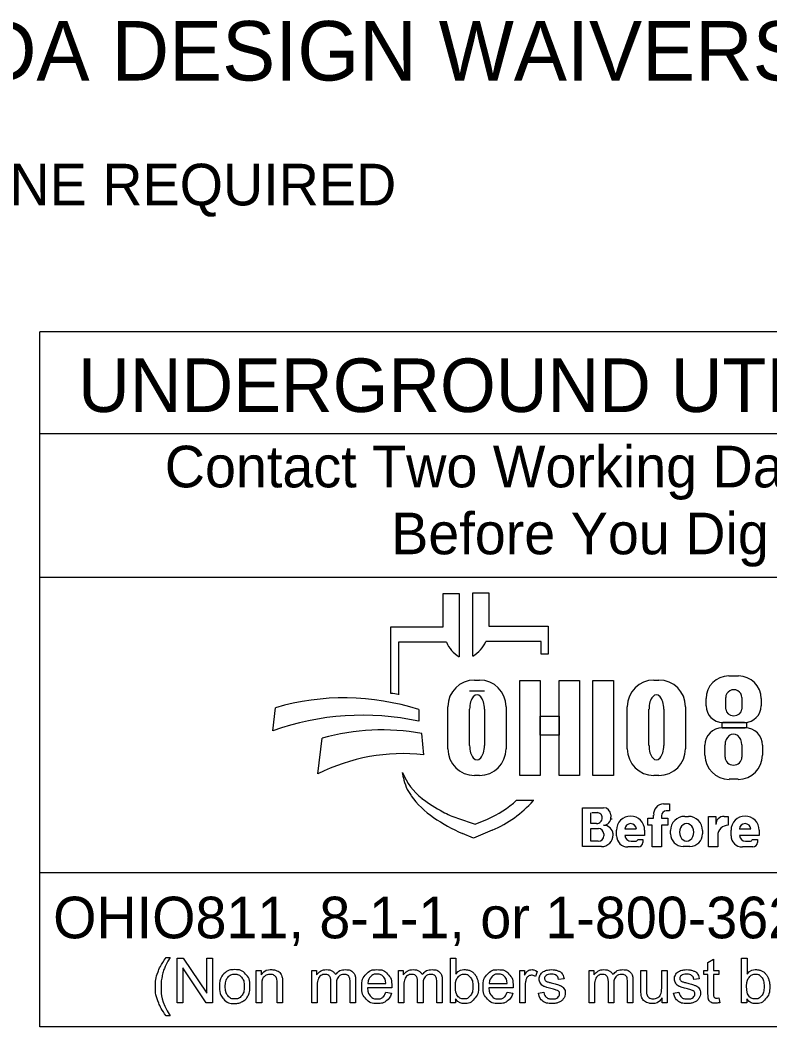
# Model space of a CAD drawing. Extents: x 6.3 to 40.3, y 9 to 31.
# Drawn here: x 8.656 to 11.176, y 11.189 to 14.574 of the extents above; entities that cross this region are included whole.
import ezdxf

# ---------------------------------------------------------------- set-up
doc = ezdxf.new("R2010")
doc.units = 0
doc.layers.add('SH_Data', color=7, linetype='Continuous')
doc.layers.add('SH_Text', color=7, linetype='Continuous')

msp = doc.modelspace()

# ---------------------------------------------------------------- linework, layer by layer
at = {"layer": 'SH_Data'}
for p, q in [((8.7221, 11.1885), (8.7221, 13.526)), ((12.9721, 13.526), (8.7221, 13.526)), ((8.7221, 13.1844), (12.9721, 13.1844)), ((8.7221, 12.7011), (12.9721, 12.7011)), ((12.9721, 11.7064), (8.7221, 11.7064)), ((12.9721, 11.1885), (8.7221, 11.1885))]:
    msp.add_line(p, q, dxfattribs=at)
at = {"layer": 'SH_Text'}
for p, q in [((10.0781, 12.534), (10.0781, 12.6455)), ((10.0781, 12.6455), (10.1318, 12.6455)), ((10.1318, 12.6455), (10.1318, 12.4334)), ((10.1775, 12.4358), (10.1775, 12.6478)), ((10.1775, 12.6478), (10.2311, 12.6478)), ((10.2311, 12.6478), (10.2311, 12.5364)), ((9.9022, 12.3101), (9.9022, 12.534)), ((9.9022, 12.534), (10.0781, 12.534)), ((10.2311, 12.5364), (10.4303, 12.5364)), ((10.4303, 12.5364), (10.4303, 12.4425)), ((9.9274, 12.4826), (9.9274, 12.3057)), ((10.0886, 12.4826), (9.9274, 12.4826)), ((10.4071, 12.4849), (10.2207, 12.4849)), ((10.4071, 12.4425), (10.4071, 12.4849)), ((10.4303, 12.4425), (10.4071, 12.4425)), ((11.0377, 12.3688), (11.0704, 12.3688)), ((10.1831, 12.3548), (10.1997, 12.3548)), ((10.7862, 12.3548), (10.8027, 12.3548)), ((10.2164, 12.3178), (10.1666, 12.3178)), ((10.9614, 12.2682), (10.9614, 12.2925)), ((11.0276, 12.2568), (11.0276, 12.2961)), ((11.0817, 12.2961), (11.0817, 12.2568)), ((11.1468, 12.2925), (11.1468, 12.2682)), ((9.5048, 12.1838), (9.5142, 12.262)), ((10.0937, 12.1234), (10.0937, 12.2654)), ((10.1666, 12.1348), (10.1666, 12.2571)), ((10.2164, 12.2571), (10.2164, 12.1348)), ((10.2891, 12.2654), (10.2891, 12.1234)), ((10.6967, 12.1234), (10.6967, 12.2654)), ((10.7696, 12.1348), (10.7696, 12.2571)), ((10.8194, 12.2571), (10.8194, 12.1348)), ((10.8922, 12.2654), (10.8922, 12.1234)), ((9.9955, 12.2555), (9.9955, 12.2166)), ((11.0156, 12.1939), (11.0929, 12.1939)), ((11.0908, 12.2122), (11.0174, 12.2122)), ((9.6566, 12.0393), (9.6713, 12.1594)), ((10.0054, 12.1749), (10.0117, 12.1039)), ((10.9577, 12.102), (10.9577, 12.136)), ((11.0252, 12.096), (11.0252, 12.137)), ((11.082, 12.137), (11.082, 12.096)), ((11.1508, 12.136), (11.1508, 12.102)), ((9.9443, 12.0264), (9.9413, 12.0443)), ((10.1997, 12.0339), (10.1831, 12.0339)), ((10.8027, 12.0339), (10.7862, 12.0339)), ((11.0698, 12.0211), (11.0387, 12.0211)), ((10.3246, 11.9505), (10.3821, 11.9505)), ((10.5459, 11.7948), (10.5459, 11.9255)), ((10.5459, 11.9255), (10.6171, 11.9255)), ((10.8185, 11.9383), (10.838, 11.9383)), ((10.838, 11.9383), (10.838, 11.9153)), ((10.1262, 11.8901), (10.1856, 11.8697)), ((10.1856, 11.8697), (10.2267, 11.8875)), ((10.5739, 11.872), (10.5739, 11.9089)), ((10.5991, 11.9089), (10.5778, 11.9089)), ((10.6409, 11.9017), (10.6409, 11.8938)), ((10.7659, 11.8669), (10.7659, 11.8899)), ((10.7659, 11.8899), (10.7852, 11.8899)), ((10.7852, 11.8899), (10.7852, 11.9004)), ((10.8113, 11.8983), (10.8113, 11.8899)), ((10.8113, 11.8899), (10.8329, 11.8899)), ((10.838, 11.9148), (10.8278, 11.9148)), ((10.8329, 11.8899), (10.8329, 11.8669)), ((10.8897, 11.8965), (10.9019, 11.8965)), ((10.97, 11.7936), (10.97, 11.8963)), ((10.97, 11.8963), (10.9945, 11.8963)), ((10.9945, 11.8963), (10.9945, 11.8694)), ((11.0218, 11.8963), (11.0356, 11.8963)), ((11.0356, 11.8963), (11.0356, 11.8666)), ((10.5933, 11.872), (10.5739, 11.872)), ((10.5739, 11.8126), (10.5739, 11.8555)), ((10.5739, 11.8555), (10.5994, 11.8555)), ((10.727, 11.8539), (10.6885, 11.8539)), ((10.7808, 11.8669), (10.7659, 11.8669)), ((10.7808, 11.7936), (10.7808, 11.8669)), ((10.8329, 11.8669), (10.8113, 11.8669)), ((10.8113, 11.8669), (10.8113, 11.7936)), ((11.112, 11.8539), (11.0734, 11.8539)), ((10.1796, 11.8226), (10.1423, 11.8391)), ((10.2429, 11.8501), (10.1796, 11.8226)), ((10.6176, 11.8373), (10.6176, 11.831)), ((10.6489, 11.8344), (10.6489, 11.8341)), ((10.6605, 11.8315), (10.6605, 11.85)), ((10.755, 11.8323), (10.6886, 11.8323)), ((10.7322, 11.8186), (10.7491, 11.8186)), ((10.7491, 11.8186), (10.7491, 11.8088)), ((10.755, 11.85), (10.755, 11.8323)), ((10.8419, 11.8379), (10.8419, 11.8487)), ((10.9497, 11.8487), (10.9497, 11.8379)), ((11.0005, 11.8317), (11.0005, 11.7936)), ((11.0454, 11.8315), (11.0454, 11.85)), ((11.1399, 11.8323), (11.0735, 11.8323)), ((11.1171, 11.8186), (11.134, 11.8186)), ((11.134, 11.8186), (11.134, 11.8088)), ((11.1399, 11.85), (11.1399, 11.8323)), ((10.6096, 11.7948), (10.5459, 11.7948)), ((10.5992, 11.8126), (10.5739, 11.8126)), ((10.7338, 11.7936), (10.6984, 11.7936)), ((10.7095, 11.8131), (10.7236, 11.8131)), ((10.8113, 11.7936), (10.7808, 11.7936)), ((10.9069, 11.7951), (10.8847, 11.7951)), ((11.0005, 11.7936), (10.97, 11.7936)), ((11.1188, 11.7936), (11.0834, 11.7936)), ((11.0944, 11.8131), (11.1085, 11.8131))]:
    msp.add_line(p, q, dxfattribs=at)
for points in [[(10.3356, 12.3538), (10.4035, 12.3538), (10.4035, 12.0338), (10.3356, 12.0338)], [(10.4677, 12.3538), (10.5357, 12.3538), (10.5357, 12.0338), (10.4677, 12.0338)], [(10.581, 12.3538), (10.6498, 12.3538), (10.6498, 12.0338), (10.581, 12.0338)], [(10.4035, 12.2339), (10.4677, 12.2339), (10.4677, 12.1699), (10.4035, 12.1699)], [(11.0153, 12.2123), (11.0969, 12.2123), (11.0969, 12.1938), (11.0153, 12.1938)]]:
    msp.add_lwpolyline(points, close=True, dxfattribs=at)
for points in [[(9.1467, 11.4223), (9.1599, 11.4223)], [(9.1835, 11.2697), (9.1835, 11.4198), (9.2038, 11.4198), (9.2828, 11.3019), (9.2828, 11.4198), (9.3018, 11.4198), (9.3018, 11.2697), (9.2815, 11.2697), (9.2025, 11.3876), (9.2025, 11.2697), (9.1835, 11.2697)], [(10.1189, 11.2697), (10.1019, 11.2697), (10.1019, 11.4198), (10.1203, 11.4198), (10.1203, 11.3663)], [(10.9679, 11.3015), (10.9679, 11.3642), (10.9543, 11.3642), (10.9543, 11.3785), (10.9679, 11.3785), (10.9679, 11.4054), (10.9863, 11.4165), (10.9863, 11.3785), (11.0047, 11.3785), (11.0047, 11.3642), (10.9863, 11.3642), (10.9863, 11.3004)], [(11.098, 11.2697), (11.0809, 11.2697), (11.0809, 11.4198), (11.0994, 11.4198), (11.0994, 11.3663)], [(9.4494, 11.2697), (9.4494, 11.3785), (9.466, 11.3785), (9.466, 11.363)], [(9.6358, 11.2697), (9.6358, 11.3785), (9.6523, 11.3785), (9.6523, 11.3631)], [(9.9272, 11.2697), (9.9272, 11.3785), (9.9437, 11.3785), (9.9437, 11.3631)], [(10.335, 11.2697), (10.335, 11.3785), (10.3516, 11.3785), (10.3516, 11.362)], [(10.5682, 11.2697), (10.5682, 11.3785), (10.5847, 11.3785), (10.5847, 11.3631)], [(10.7425, 11.3111), (10.7425, 11.3785), (10.761, 11.3785), (10.761, 11.3182)], [(10.8122, 11.3202), (10.8122, 11.3785), (10.8307, 11.3785), (10.8307, 11.2697), (10.8142, 11.2697)], [(9.7834, 11.3443), (9.7834, 11.2697), (9.7649, 11.2697), (9.7649, 11.3381)], [(10.0747, 11.3443), (10.0747, 11.2697), (10.0563, 11.2697), (10.0563, 11.3381)], [(10.3941, 11.375), (10.3876, 11.3579)], [(10.484, 11.3503), (10.4659, 11.3479)], [(10.7157, 11.3443), (10.7157, 11.2697), (10.6973, 11.2697), (10.6973, 11.3381)], [(10.9386, 11.3503), (10.9205, 11.3479)], [(9.4679, 11.329), (9.4679, 11.2697), (9.4494, 11.2697)], [(9.5378, 11.3365), (9.5378, 11.2697), (9.5194, 11.2697), (9.5194, 11.3358)], [(9.6543, 11.3261), (9.6543, 11.2697), (9.6358, 11.2697)], [(9.7189, 11.3328), (9.7189, 11.2697), (9.7005, 11.2697), (9.7005, 11.3403)], [(9.9046, 11.3193), (9.8234, 11.3193)], [(9.8245, 11.3344), (9.8852, 11.3344)], [(9.9456, 11.3261), (9.9456, 11.2697), (9.9272, 11.2697)], [(10.0103, 11.3328), (10.0103, 11.2697), (9.9919, 11.2697), (9.9919, 11.3403)], [(10.3126, 11.3193), (10.2314, 11.3193)], [(10.2325, 11.3344), (10.2932, 11.3344)], [(10.3534, 11.3266), (10.3534, 11.2697), (10.335, 11.2697)], [(10.5866, 11.3261), (10.5866, 11.2697), (10.5682, 11.2697)], [(10.6513, 11.3328), (10.6513, 11.2697), (10.6329, 11.2697), (10.6329, 11.3403)], [(9.885, 11.3048), (9.9041, 11.3024)], [(10.1189, 11.2833), (10.1189, 11.2697)], [(10.293, 11.3048), (10.3121, 11.3024)], [(10.3976, 11.3022), (10.4158, 11.305)], [(10.8142, 11.2697), (10.8142, 11.2857)], [(10.8522, 11.3022), (10.8704, 11.305)], [(11.0047, 11.2861), (11.0074, 11.2698)], [(11.098, 11.2833), (11.098, 11.2697)], [(9.1599, 11.2255), (9.1467, 11.2255)]]:
    msp.add_lwpolyline(points, dxfattribs=at)
for centre, radius, start, end in [((10.1799, 12.5194), 0.0985, 201.9296, 240.7469), ((10.1293, 12.5217), 0.0985, 299.2531, 338.0704), ((11.0377, 12.2925), 0.0763, 90, 180), ((11.0704, 12.2925), 0.0763, 0, 90), ((10.1831, 12.2654), 0.0895, 90, 180), ((10.1997, 12.2654), 0.0895, 0, 90), ((10.7862, 12.2654), 0.0895, 90, 180), ((10.8027, 12.2654), 0.0895, 0, 90), ((9.7443, 11.4759), 0.8191, 72.1402, 106.3144), ((9.7741, 11.5012), 0.8191, 79.2074, 81.0007), ((11.0174, 12.2682), 0.056, 180, 270), ((11.0908, 12.2682), 0.056, 270, 0), ((9.8074, 11.3448), 0.8919, 77.8238, 109.8274), ((11.0156, 12.136), 0.0579, 90, 180), ((11.0929, 12.136), 0.0579, 0, 90), ((9.8713, 11.4551), 0.7322, 79.44, 105.8467), ((10.1831, 12.1234), 0.0895, 180, 270), ((10.1997, 12.1234), 0.0895, 270, 0), ((10.7862, 12.1234), 0.0895, 180, 270), ((10.8027, 12.1234), 0.0895, 270, 0), ((9.9433, 11.4719), 0.6357, 83.8248, 116.8021), ((11.0387, 12.102), 0.081, 180, 270), ((11.0698, 12.102), 0.081, 270, 0), ((10.1287, 12.1164), 0.2008, 201.0457, 232.5314), ((10.0856, 12.0505), 0.1433, 189.6817, 216.0884), ((10.2193, 12.1479), 0.3088, 216.0884, 235.7167), ((10.3212, 12.3676), 0.5173, 232.5314, 241.794), ((10.0833, 12.2179), 0.3602, 293.4582, 312.0712), ((10.0833, 12.2179), 0.401, 293.4582, 317.8286), ((10.6171, 11.9017), 0.0238, 0, 90), ((10.8185, 11.9047), 0.0335, 90, 187.5187), ((10.3858, 12.3922), 0.6044, 235.7167, 246.2325), ((10.236, 12.2088), 0.3371, 241.794, 250.9821), ((10.5933, 11.8907), 0.0187, 270, 2.0582), ((10.5952, 11.8921), 0.0169, 357.8325, 90), ((10.6167, 11.891), 0.0243, 270, 6.6529), ((10.6273, 11.8895), 0.0175, 347.4023, 0), ((10.7077, 11.85), 0.0473, 0, 180), ((10.8278, 11.8983), 0.0165, 90, 180), ((10.8897, 11.8487), 0.0478, 90, 180), ((10.9019, 11.8487), 0.0478, 0, 90), ((11.0214, 11.8694), 0.0269, 89.2449, 180), ((11.0927, 11.85), 0.0473, 0, 180), ((10.5994, 11.8373), 0.0181, 0, 90), ((10.6168, 11.8346), 0.0321, 4.0748, 90), ((10.7078, 11.8529), 0.0193, 2.9632, 177.0368), ((11.0354, 11.8317), 0.0349, 89.6033, 180), ((11.0927, 11.8529), 0.0193, 2.9632, 177.0368), ((10.5992, 11.831), 0.0184, 270, 0), ((10.6096, 11.8341), 0.0393, 270, 0), ((10.616, 11.8344), 0.033, 0, 11.7502), ((10.6984, 11.8315), 0.038, 180, 270), ((10.7095, 11.8341), 0.021, 184.827, 270), ((10.7236, 11.8224), 0.00938, 270, 335.9979), ((10.8847, 11.8379), 0.0428, 180, 270), ((10.9069, 11.8379), 0.0428, 270, 0), ((11.0834, 11.8315), 0.038, 180, 270), ((11.0944, 11.8341), 0.021, 184.827, 270), ((11.1085, 11.8224), 0.00938, 270, 335.9979), ((10.7338, 11.8088), 0.0152, 270, 0), ((11.1188, 11.8088), 0.0152, 270, 0)]:
    msp.add_arc(centre, radius, start, end, dxfattribs=at)
for centre, major_axis, ratio, start_param, end_param in [((10.1915, 12.2571), (0, 0.0484), 0.514403, 4.712389, 7.853982), ((10.7945, 12.2571), (0, 0.0484), 0.514403, 4.712389, 7.853982), ((11.0546, 12.2961), (0.0271, 0), 0.969373, 0, 3.141593), ((11.0546, 12.2568), (0.0271, 0), 0.818453, 3.141593, 6.283185), ((11.0536, 12.137), (0, 0.0358), 0.794529, 4.712389, 7.853982), ((10.1915, 12.1348), (0, 0.0484), 0.514403, 1.570796, 4.712389), ((10.7945, 12.1348), (0, 0.0484), 0.514403, 1.570796, 4.712389), ((11.0536, 12.096), (0.0284, 0), 0.959837, 3.141593, 6.283185), ((10.8963, 11.8433), (0, 0.029), 0.832186, 4.712389, 7.853982), ((10.8963, 11.8433), (0, 0.0302), 0.797287, 1.570796, 4.712389)]:
    msp.add_ellipse(centre, major_axis=major_axis, ratio=ratio, start_param=start_param, end_param=end_param, dxfattribs=at)
for points in [[(9.1467, 11.2255), (9.1315, 11.2447), (9.1209, 11.2705), (9.1103, 11.2963), (9.1103, 11.324), (9.1103, 11.3484), (9.1182, 11.3707), (9.1275, 11.3966), (9.1467, 11.4223)], [(9.1599, 11.4223), (9.1475, 11.401), (9.1435, 11.3919), (9.1373, 11.3778), (9.1337, 11.3624), (9.1293, 11.3433), (9.1293, 11.3239), (9.1293, 11.2746), (9.1599, 11.2255)], [(9.326, 11.3241), (9.326, 11.3543), (9.3427, 11.3688), (9.3568, 11.3809), (9.3769, 11.3809), (9.3994, 11.3809), (9.4136, 11.3662), (9.4278, 11.3515), (9.4278, 11.3256), (9.4278, 11.3046), (9.4215, 11.2926), (9.4152, 11.2806), (9.4032, 11.2739), (9.3912, 11.2672), (9.3769, 11.2672), (9.3541, 11.2672), (9.34, 11.2819), (9.326, 11.2965), (9.326, 11.3241)], [(9.466, 11.363), (9.478, 11.3809), (9.5006, 11.3809), (9.5105, 11.3809), (9.5187, 11.3774), (9.5269, 11.3738), (9.531, 11.3681), (9.5351, 11.3623), (9.5368, 11.3545), (9.5378, 11.3493), (9.5378, 11.3365)], [(9.6523, 11.3631), (9.6575, 11.3711), (9.666, 11.376), (9.6745, 11.3809), (9.6853, 11.3809), (9.6974, 11.3809), (9.7052, 11.3759), (9.7129, 11.3708), (9.7161, 11.3618), (9.729, 11.3809), (9.7497, 11.3809), (9.7659, 11.3809), (9.7746, 11.3719), (9.7834, 11.363), (9.7834, 11.3443)], [(9.9041, 11.3024), (9.8996, 11.2857), (9.8874, 11.2765), (9.8752, 11.2672), (9.8563, 11.2672), (9.8324, 11.2672), (9.8184, 11.2819), (9.8044, 11.2966), (9.8044, 11.3231), (9.8044, 11.3506), (9.8186, 11.3657), (9.8327, 11.3809), (9.8552, 11.3809), (9.877, 11.3809), (9.8909, 11.366), (9.9047, 11.3512), (9.9047, 11.3242), (9.9047, 11.3226), (9.9046, 11.3193)], [(9.9437, 11.3631), (9.9488, 11.3711), (9.9573, 11.376), (9.9658, 11.3809), (9.9767, 11.3809), (9.9888, 11.3809), (9.9965, 11.3759), (10.0043, 11.3708), (10.0074, 11.3618), (10.0204, 11.3809), (10.0411, 11.3809), (10.0573, 11.3809), (10.066, 11.3719), (10.0747, 11.363), (10.0747, 11.3443)], [(10.1203, 11.3663), (10.132, 11.3809), (10.1501, 11.3809), (10.1601, 11.3809), (10.1691, 11.3768), (10.1781, 11.3728), (10.1838, 11.3655), (10.1896, 11.3582), (10.1929, 11.3478), (10.1962, 11.3375), (10.1962, 11.3257), (10.1962, 11.2978), (10.1824, 11.2825), (10.1685, 11.2672), (10.1492, 11.2672), (10.1299, 11.2672), (10.1189, 11.2833)], [(10.3121, 11.3024), (10.3076, 11.2857), (10.2954, 11.2765), (10.2832, 11.2672), (10.2643, 11.2672), (10.2404, 11.2672), (10.2264, 11.2819), (10.2124, 11.2966), (10.2124, 11.3231), (10.2124, 11.3506), (10.2266, 11.3657), (10.2407, 11.3809), (10.2632, 11.3809), (10.285, 11.3809), (10.2989, 11.366), (10.3127, 11.3512), (10.3127, 11.3242), (10.3127, 11.3226), (10.3126, 11.3193)], [(10.3516, 11.362), (10.3579, 11.3735), (10.3633, 11.3772), (10.3687, 11.3809), (10.3751, 11.3809), (10.3844, 11.3809), (10.3941, 11.375)], [(10.4158, 11.305), (10.4173, 11.294), (10.4244, 11.2882), (10.4314, 11.2824), (10.4441, 11.2824), (10.4568, 11.2824), (10.463, 11.2875), (10.4691, 11.2927), (10.4691, 11.2997), (10.4691, 11.3059), (10.4637, 11.3095), (10.4599, 11.312), (10.4448, 11.3158), (10.4245, 11.3209), (10.4166, 11.3247), (10.4088, 11.3284), (10.4047, 11.335), (10.4007, 11.3416), (10.4007, 11.3496), (10.4007, 11.3568), (10.404, 11.363), (10.4074, 11.3692), (10.4131, 11.3733), (10.4174, 11.3765), (10.4249, 11.3787), (10.4323, 11.3809), (10.4408, 11.3809), (10.4536, 11.3809), (10.4633, 11.3772), (10.473, 11.3735), (10.4776, 11.3672), (10.4823, 11.3609), (10.484, 11.3503)], [(10.5847, 11.3631), (10.5898, 11.3711), (10.5983, 11.376), (10.6068, 11.3809), (10.6177, 11.3809), (10.6298, 11.3809), (10.6375, 11.3759), (10.6453, 11.3708), (10.6484, 11.3618), (10.6614, 11.3809), (10.6821, 11.3809), (10.6983, 11.3809), (10.707, 11.3719), (10.7157, 11.363), (10.7157, 11.3443)], [(10.8704, 11.305), (10.8719, 11.294), (10.879, 11.2882), (10.886, 11.2824), (10.8986, 11.2824), (10.9114, 11.2824), (10.9175, 11.2875), (10.9237, 11.2927), (10.9237, 11.2997), (10.9237, 11.3059), (10.9183, 11.3095), (10.9144, 11.312), (10.8994, 11.3158), (10.8791, 11.3209), (10.8712, 11.3247), (10.8634, 11.3284), (10.8593, 11.335), (10.8553, 11.3416), (10.8553, 11.3496), (10.8553, 11.3568), (10.8586, 11.363), (10.8619, 11.3692), (10.8677, 11.3733), (10.872, 11.3765), (10.8794, 11.3787), (10.8869, 11.3809), (10.8954, 11.3809), (10.9082, 11.3809), (10.9179, 11.3772), (10.9276, 11.3735), (10.9322, 11.3672), (10.9368, 11.3609), (10.9386, 11.3503)], [(11.0994, 11.3663), (11.111, 11.3809), (11.1292, 11.3809), (11.1392, 11.3809), (11.1482, 11.3768), (11.1571, 11.3728), (11.1629, 11.3655), (11.1687, 11.3582), (11.172, 11.3478), (11.1753, 11.3375), (11.1753, 11.3257), (11.1753, 11.2978), (11.1614, 11.2825), (11.1476, 11.2672), (11.1282, 11.2672), (11.109, 11.2672), (11.098, 11.2833)], [(9.345, 11.3241), (9.345, 11.3032), (9.354, 11.2928), (9.3631, 11.2824), (9.3769, 11.2824), (9.3906, 11.2824), (9.3997, 11.2928), (9.4088, 11.3033), (9.4088, 11.3247), (9.4088, 11.3449), (9.3997, 11.3553), (9.3905, 11.3657), (9.3769, 11.3657), (9.3631, 11.3657), (9.354, 11.3553), (9.345, 11.345), (9.345, 11.3241)], [(9.5194, 11.3358), (9.5194, 11.3471), (9.5172, 11.3526), (9.5151, 11.3582), (9.5096, 11.3615), (9.5041, 11.3649), (9.4967, 11.3649), (9.485, 11.3649), (9.4764, 11.3574), (9.4679, 11.3499), (9.4679, 11.329)], [(9.7005, 11.3403), (9.7005, 11.3526), (9.696, 11.3587), (9.6915, 11.3649), (9.6812, 11.3649), (9.6734, 11.3649), (9.6668, 11.3608), (9.6602, 11.3567), (9.6572, 11.3488), (9.6543, 11.3409), (9.6543, 11.3261)], [(9.7649, 11.3381), (9.7649, 11.3492), (9.7631, 11.3541), (9.7614, 11.3589), (9.7566, 11.3619), (9.7519, 11.3649), (9.7456, 11.3649), (9.7341, 11.3649), (9.7265, 11.3572), (9.7189, 11.3496), (9.7189, 11.3328)], [(9.8852, 11.3344), (9.884, 11.3482), (9.8783, 11.3551), (9.8695, 11.3658), (9.8554, 11.3658), (9.8427, 11.3658), (9.8341, 11.3572), (9.8254, 11.3487), (9.8245, 11.3344)], [(9.9919, 11.3403), (9.9919, 11.3526), (9.9874, 11.3587), (9.9829, 11.3649), (9.9726, 11.3649), (9.9648, 11.3649), (9.9582, 11.3608), (9.9516, 11.3567), (9.9486, 11.3488), (9.9456, 11.3409), (9.9456, 11.3261)], [(10.0563, 11.3381), (10.0563, 11.3492), (10.0545, 11.3541), (10.0527, 11.3589), (10.048, 11.3619), (10.0433, 11.3649), (10.0369, 11.3649), (10.0255, 11.3649), (10.0179, 11.3572), (10.0103, 11.3496), (10.0103, 11.3328)], [(10.1187, 11.3249), (10.1187, 11.3053), (10.124, 11.2966), (10.1327, 11.2824), (10.1475, 11.2824), (10.1596, 11.2824), (10.1684, 11.2929), (10.1772, 11.3034), (10.1772, 11.3242), (10.1772, 11.3455), (10.1688, 11.3556), (10.1603, 11.3658), (10.1484, 11.3658), (10.1363, 11.3658), (10.1275, 11.3553), (10.1187, 11.3448), (10.1187, 11.3249)], [(10.2932, 11.3344), (10.292, 11.3482), (10.2863, 11.3551), (10.2775, 11.3658), (10.2634, 11.3658), (10.2507, 11.3658), (10.242, 11.3572), (10.2334, 11.3487), (10.2325, 11.3344)], [(10.3876, 11.3579), (10.3809, 11.3619), (10.3741, 11.3619), (10.3681, 11.3619), (10.3633, 11.3583), (10.3585, 11.3546), (10.3565, 11.3482), (10.3534, 11.3383), (10.3534, 11.3266)], [(10.4659, 11.3479), (10.4647, 11.3563), (10.4588, 11.3611), (10.4529, 11.3658), (10.4421, 11.3658), (10.4294, 11.3658), (10.424, 11.3616), (10.4185, 11.3574), (10.4185, 11.3517), (10.4185, 11.3481), (10.4208, 11.3453), (10.4231, 11.3423), (10.4279, 11.3403), (10.4306, 11.3393), (10.4442, 11.3356), (10.4638, 11.3304), (10.4715, 11.3271), (10.4793, 11.3237), (10.4837, 11.3174), (10.4881, 11.3111), (10.4881, 11.3016), (10.4881, 11.2924), (10.4827, 11.2843), (10.4774, 11.2762), (10.4672, 11.2717), (10.457, 11.2672), (10.4442, 11.2672), (10.423, 11.2672), (10.4118, 11.2761), (10.4007, 11.2849), (10.3976, 11.3022)], [(10.6329, 11.3403), (10.6329, 11.3526), (10.6284, 11.3587), (10.6239, 11.3649), (10.6136, 11.3649), (10.6058, 11.3649), (10.5992, 11.3608), (10.5926, 11.3567), (10.5896, 11.3488), (10.5866, 11.3409), (10.5866, 11.3261)], [(10.6973, 11.3381), (10.6973, 11.3492), (10.6955, 11.3541), (10.6937, 11.3589), (10.689, 11.3619), (10.6843, 11.3649), (10.6779, 11.3649), (10.6665, 11.3649), (10.6589, 11.3572), (10.6513, 11.3496), (10.6513, 11.3328)], [(10.9205, 11.3479), (10.9193, 11.3563), (10.9134, 11.3611), (10.9075, 11.3658), (10.8967, 11.3658), (10.884, 11.3658), (10.8786, 11.3616), (10.8731, 11.3574), (10.8731, 11.3517), (10.8731, 11.3481), (10.8754, 11.3453), (10.8776, 11.3423), (10.8825, 11.3403), (10.8852, 11.3393), (10.8988, 11.3356), (10.9183, 11.3304), (10.9261, 11.3271), (10.9339, 11.3237), (10.9383, 11.3174), (10.9427, 11.3111), (10.9427, 11.3016), (10.9427, 11.2924), (10.9373, 11.2843), (10.9319, 11.2762), (10.9218, 11.2717), (10.9116, 11.2672), (10.8988, 11.2672), (10.8775, 11.2672), (10.8664, 11.2761), (10.8553, 11.2849), (10.8522, 11.3022)], [(11.0978, 11.3249), (11.0978, 11.3053), (11.1031, 11.2966), (11.1118, 11.2824), (11.1266, 11.2824), (11.1387, 11.2824), (11.1475, 11.2929), (11.1563, 11.3034), (11.1563, 11.3242), (11.1563, 11.3455), (11.1478, 11.3556), (11.1394, 11.3658), (11.1274, 11.3658), (11.1154, 11.3658), (11.1066, 11.3553), (11.0978, 11.3448), (11.0978, 11.3249)], [(9.8234, 11.3193), (9.8245, 11.3014), (9.8336, 11.2919), (9.8427, 11.2824), (9.8563, 11.2824), (9.8665, 11.2824), (9.8737, 11.2877), (9.8808, 11.2931), (9.885, 11.3048)], [(10.2314, 11.3193), (10.2325, 11.3014), (10.2416, 11.2919), (10.2507, 11.2824), (10.2643, 11.2824), (10.2745, 11.2824), (10.2817, 11.2877), (10.2888, 11.2931), (10.293, 11.3048)], [(10.8142, 11.2857), (10.8015, 11.2672), (10.7797, 11.2672), (10.7701, 11.2672), (10.7617, 11.2709), (10.7534, 11.2746), (10.7493, 11.2802), (10.7453, 11.2858), (10.7437, 11.2939), (10.7425, 11.2993), (10.7425, 11.3111)], [(10.761, 11.3182), (10.761, 11.3037), (10.7621, 11.2987), (10.7638, 11.2914), (10.7695, 11.2873), (10.7751, 11.2832), (10.7834, 11.2832), (10.7917, 11.2832), (10.7989, 11.2874), (10.8062, 11.2917), (10.8092, 11.299), (10.8122, 11.3063), (10.8122, 11.3202)], [(11.0074, 11.2698), (10.9996, 11.2682), (10.9935, 11.2682), (10.9834, 11.2682), (10.9779, 11.2713), (10.9724, 11.2745), (10.9701, 11.2797), (10.9679, 11.2849), (10.9679, 11.3015)], [(10.9863, 11.3004), (10.9863, 11.2925), (10.9873, 11.2903), (10.9882, 11.288), (10.9904, 11.2867), (10.9926, 11.2853), (10.9967, 11.2853), (10.9997, 11.2853), (11.0047, 11.2861)]]:
    msp.add_open_spline(points, degree=3, dxfattribs=at)

# ---------------------------------------------------------------- texts
for s, height, p in [('ADA DESIGN WAIVERS', 0.2, (8.339, 14.3713)), ('NONE REQUIRED', 0.14, (8.339, 13.9513)), ('UNDERGROUND UTILITIES', 0.18, (8.8503, 13.2564)), ('Contact Two Working Days', 0.14, (9.1418, 13.0029)), ('Before You Dig', 0.14, (9.9029, 12.7779)), ('OHIO811, 8-1-1, or 1-800-362-2764', 0.14, (8.7666, 11.4863))]:
    msp.add_text(s, height=height, dxfattribs=at).set_placement(p)

doc.saveas('drawing.dxf')
